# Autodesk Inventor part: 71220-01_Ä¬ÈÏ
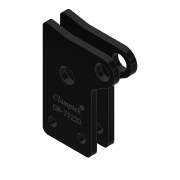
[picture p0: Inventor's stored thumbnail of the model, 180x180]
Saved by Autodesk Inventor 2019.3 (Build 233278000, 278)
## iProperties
Created: 2010-06
Part Number: 71220-01_Ä¬ÈÏ
Material: Ogólny
Document SubType Name: Modeling
Designer: CADENGINEERING4
Density: 1 g/cm^3
Appearance: Gładki — czarny
Author: CADENGINEERING4
Revision Number: ÈÎºÎ
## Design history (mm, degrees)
feature "NONE"
feature "NONE:1"
node "Bryła1"
node "Bryła2"
